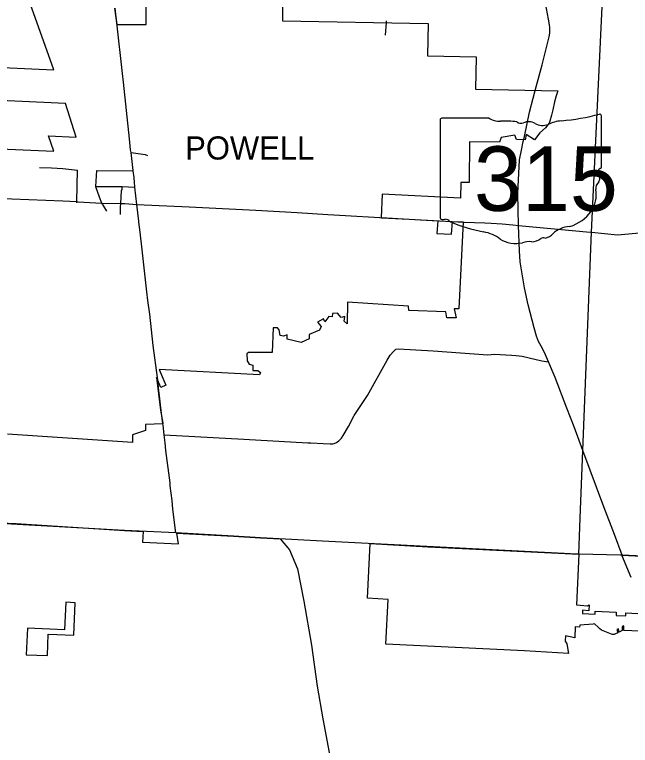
# Model space of a CAD drawing. Extents: x 1729596 to 1925846, y 659247 to 911751.
# Drawn here: x 1805067 to 1818365, y 774852 to 790627 of the extents above; entities that cross this region are included whole.
import ezdxf

# ---------------------------------------------------------------- set-up
doc = ezdxf.new("R2010")
doc.units = 0
for name, color, linetype in [('GM_X_City_Street', 7, 'Continuous'), ('GM_X_Corporation', 7, 'Continuous'), ('GM_X_Corporation_Text', 7, 'Continuous'), ('GM_X_County', 7, 'Continuous'), ('GM_X_County_Road', 7, 'Continuous'), ('GM_X_State_Route', 7, 'Continuous'), ('GM_X_State_Shield', 7, 'Continuous'), ('GM_X_Township', 7, 'Continuous'), ('GM_X_Township_Road', 7, 'Continuous')]:
    doc.layers.add(name, color=color, linetype=linetype)

msp = doc.modelspace()

# ---------------------------------------------------------------- linework, layer by layer
at = {"layer": 'GM_X_City_Street'}
for points in [[(1813075, 790181), (1813101, 790456), (1813101, 790491)], [(1807398, 789353), (1807271, 790449), (1807271, 790450)], [(1807628, 787263), (1807582, 787650), (1807569, 787707), (1807549, 787947), (1807419, 789169), (1807398, 789353)], [(1807582, 787650), (1807889, 787607), (1807940, 787583)], [(1805605, 787326), (1805861, 787317), (1806111, 787304), (1806423, 787273)], [(1806408, 786563), (1806408, 786590), (1806423, 787273)], [(1806969, 786525), (1806968, 786526), (1806959, 786540), (1806951, 786560), (1806899, 786685), (1806822, 786909), (1806822, 786916), (1806843, 787260)], [(1806843, 787260), (1807629, 787255)], [(1807709, 786531), (1807666, 786900), (1807648, 787114), (1807629, 787255), (1807628, 787263)], [(1806822, 786916), (1807392, 786917), (1807666, 786900)], [(1807356, 786480), (1807360, 786549), (1807374, 786826), (1807390, 786857), (1807392, 786917)], [(1807056, 786387), (1806969, 786525)], [(1807356, 786314), (1807356, 786472), (1807356, 786480)], [(1807750, 786168), (1807709, 786531)], [(1807947, 784457), (1807922, 784645), (1807821, 785550), (1807776, 785934), (1807752, 786147), (1807750, 786168)], [(1808158, 782748), (1808154, 782791), (1808057, 783484), (1807988, 784161), (1807947, 784457)]]:
    msp.add_lwpolyline(points, dxfattribs=at)
at = {"layer": 'GM_X_Corporation'}
for points in [[(1804164, 789513), (1805912, 789433), (1805403, 790869)], [(1810855, 790858), (1810855, 790494), (1814000, 790437), (1813987, 789737), (1815036, 789718), (1815023, 789018), (1816797, 788985), (1816759, 788876), (1816729, 788747), (1816691, 788572), (1816660, 788458), (1816629, 788327), (1816608, 788285), (1816530, 788186), (1816408, 788075), (1816292, 787922), (1816117, 788037), (1816092, 787927), (1815906, 787930), (1815870, 788024), (1815574, 787972), (1815539, 787875), (1814889, 787878), (1814886, 787002), (1814701, 787002), (1814699, 786665), (1813003, 786749), (1812982, 786246), (1813591, 786209), (1814206, 786179), (1814187, 785899), (1814503, 785888), (1814522, 786163), (1814757, 786152), (1814657, 784274), (1814557, 784275), (1814602, 784081), (1814401, 784079), (1814383, 784214), (1813584, 784242), (1813574, 784337), (1812256, 784419), (1812247, 783951), (1812181, 784013), (1812199, 784114), (1812120, 784091), (1812040, 784183), (1811933, 784175), (1811928, 784105), (1811851, 784108), (1811768, 783996), (1811741, 784063), (1811608, 783989), (1811689, 783895), (1811653, 783814), (1811428, 783724), (1811428, 783627), (1811259, 783546), (1810952, 783622), (1810951, 783717), (1810873, 783683), (1810802, 783700), (1810777, 783821), (1810744, 783865), (1810651, 783866), (1810628, 783334), (1810117, 783337), (1810085, 783303), (1810089, 783153), (1810132, 783082), (1810210, 783063), (1810211, 782942), (1810317, 782943), (1810375, 782902), (1810352, 782851), (1808190, 782970), (1808330, 782630), (1808222, 782579), (1808132, 782796), (1808214, 782091), (1808266, 781809), (1808269, 781795), (1807897, 781781), (1807895, 781653), (1807614, 781559), (1807613, 781390), (1804914, 781573)], [(1807231, 790763), (1807256, 790572), (1807273, 790417), (1807905, 790417), (1807905, 790798)], [(1804086, 787756), (1805912, 787678), (1805802, 788014), (1806394, 787983), (1806164, 788712), (1804132, 788800)], [(1803430, 774349), (1803483, 775420), (1803558, 776945), (1803585, 777445), (1803603, 778383), (1803634, 779704), (1803704, 779701), (1805102, 779639), (1807438, 779491), (1807843, 779471), (1807831, 779242), (1808605, 779201), (1808568, 779436), (1809792, 779366), (1810377, 779331), (1810804, 779309), (1811005, 779073), (1811178, 778662), (1811316, 777964), (1811480, 777017), (1811604, 776133), (1811724, 775429), (1811904, 774466)], [(1818738, 777311), (1818223, 777335), (1818227, 777430), (1818185, 777409), (1818187, 777330), (1818125, 777299), (1818105, 777371), (1818074, 777354), (1818094, 777281), (1818047, 777262), (1818016, 777249), (1817997, 777245), (1817979, 777246), (1817957, 777251), (1817918, 777268), (1817743, 777338), (1817706, 777368), (1817659, 777415), (1817598, 777471), (1817589, 777474), (1817558, 777471), (1817270, 777444), (1817267, 777407), (1817175, 777415), (1817162, 777174), (1816963, 777214), (1816955, 777103), (1816990, 777043), (1817028, 776838), (1816077, 776890), (1813084, 777036), (1813135, 778003), (1812688, 778029), (1812748, 779209), (1813989, 779140), (1817250, 778977), (1817198, 777883), (1817437, 777868), (1817477, 777883), (1817466, 777757), (1817333, 777768), (1817329, 777699), (1817602, 777686), (1817606, 777753), (1818060, 777725), (1818058, 777659), (1818265, 777648), (1818267, 777712), (1818526, 777699)], [(1818382, 778477), (1818182, 778957), (1823932, 778674)]]:
    msp.add_lwpolyline(points, dxfattribs=at)
msp.add_lwpolyline([(1805774, 776791), (1805793, 777251), (1806343, 777229), (1806372, 777932), (1806172, 777941), (1806147, 777344), (1805342, 777383), (1805319, 776810)], close=True, dxfattribs=at)
at = {"layer": 'GM_X_County'}
msp.add_lwpolyline([(1823936, 778682), (1818187, 778957), (1818151, 778958), (1817250, 778977), (1817214, 778979), (1811853, 779256), (1810377, 779331), (1809792, 779366), (1808550, 779443), (1807438, 779491), (1803704, 779701), (1803634, 779704), (1801375, 779790), (1799802, 779890), (1799218, 779920), (1797967, 779971), (1795507, 780094), (1795095, 780091), (1793746, 780223), (1793171, 780273)], dxfattribs=at)
at = {"layer": 'GM_X_County_Road'}
for points in [[(1807271, 790450), (1807231, 790763)], [(1808203, 782333), (1808174, 782570), (1808158, 782748)], [(1808272, 781763), (1808269, 781795), (1808233, 782081), (1808210, 782272), (1808203, 782333)], [(1808550, 779443), (1808487, 779955), (1808466, 780137), (1808429, 780452), (1808423, 780522), (1808336, 781219), (1808318, 781382), (1808298, 781556), (1808272, 781763)]]:
    msp.add_lwpolyline(points, dxfattribs=at)
at = {"layer": 'GM_X_State_Route'}
for points in [[(1816266, 788827), (1816308, 788989), (1816463, 789546), (1816611, 790147), (1816623, 790230), (1816624, 790350), (1816620, 790409), (1816599, 790530), (1816533, 790876), (1816487, 791123), (1816430, 791427), (1816402, 791554), (1816384, 791615), (1816350, 791700), (1816268, 791852), (1816208, 791960), (1816169, 792032), (1816020, 792294), (1815964, 792391), (1815825, 792638), (1815801, 792684), (1815789, 792708)], [(1816069, 787957), (1816079, 787999), (1816187, 788523), (1816266, 788827)], [(1816013, 787700), (1816053, 787885), (1816069, 787957)], [(1815949, 786077), (1815949, 786077), (1815938, 786769), (1815968, 787495), (1816013, 787700)], [(1804441, 786683), (1805006, 786649), (1806106, 786604), (1806408, 786590), (1806429, 786589), (1806951, 786560), (1807360, 786549), (1807446, 786547), (1807709, 786531), (1808840, 786478), (1810274, 786407), (1811167, 786357), (1811832, 786309), (1812210, 786294), (1812953, 786246)], [(1812953, 786246), (1812990, 786243), (1813591, 786209), (1814771, 786150), (1814772, 786150)], [(1814772, 786150), (1815220, 786136), (1815357, 786129), (1815594, 786109), (1815826, 786090), (1815949, 786077)], [(1815949, 786077), (1816340, 786036), (1817421, 785936), (1817504, 785931), (1817524, 785929), (1818089, 785876), (1818484, 785913), (1818908, 785967), (1819089, 785999), (1819665, 786100), (1819718, 786112), (1820036, 786168), (1820128, 786185), (1820241, 786200), (1820367, 786198), (1820698, 786179), (1821320, 786143), (1821549, 786130)], [(1818019, 779405), (1817795, 780002), (1817338, 781221), (1817148, 781730), (1816994, 782133), (1816739, 782797), (1816596, 783133), (1816530, 783286), (1816466, 783417), (1816381, 783573), (1816336, 783687), (1816285, 783865), (1816160, 784364), (1816076, 784730), (1816020, 785073), (1815987, 785293), (1815970, 785528), (1815949, 786077)], [(1818187, 778957), (1818019, 779405)]]:
    msp.add_lwpolyline(points, dxfattribs=at)
at = {"layer": 'GM_X_State_Shield'}
for p, q in [((1817739, 787338), (1817739, 788444)), ((1817739, 787338), (1817739, 788444)), ((1814259, 788355), (1814259, 786242)), ((1814259, 788355), (1814259, 786242)), ((1815312, 788391), (1814293, 788391)), ((1815312, 788391), (1814293, 788391)), ((1817739, 787339), (1817739, 787338)), ((1817739, 787339), (1817739, 787338))]:
    msp.add_line(p, q, dxfattribs=at)
for centre, major_axis, start_param, end_param in [((1816499, 791273), (3691, 0), 4.814394, 5.042369), ((1816499, 791273), (3691, 0), 4.814394, 5.042369), ((1817700, 788448), (38.7, 0), 6.141152, 7.989035), ((1817700, 788448), (38.7, 0), 6.141152, 7.989035), ((1814298, 788360), (40.3, 0), 1.712693, 3.28349), ((1814298, 788360), (40.3, 0), 1.712693, 3.28349), ((1815555, 788637), (391, 0), 4.042523, 4.731795), ((1815555, 788637), (391, 0), 4.042523, 4.731795), ((1815684, 787205), (1404, 0), 1.404758, 1.657858), ((1815684, 787205), (1404, 0), 1.404758, 1.657858), ((1816003, 788371), (113, 0), 3.836095, 5.185415), ((1816003, 788371), (113, 0), 3.836095, 5.185415), ((1816169, 788126), (235, 0), 0.950623, 2.079405), ((1816169, 788126), (235, 0), 0.950623, 2.079405), ((1816472, 788461), (282, 0), 4.081561, 5.145723), ((1816472, 788461), (282, 0), 4.081561, 5.145723), ((1816970, 787746), (743, 0), 1.699011, 2.107814), ((1816970, 787746), (743, 0), 1.699011, 2.107814), ((1817698, 787334), (41.5, 0), 5.05454, 6.418171), ((1817698, 787334), (41.5, 0), 5.05454, 6.418171), ((1817730, 787257), (60, 0), 1.883978, 3.671073), ((1817730, 787257), (60, 0), 1.883978, 3.671073), ((1817349, 787117), (360, 0), 5.934695, 6.695948), ((1817349, 787117), (360, 0), 5.934695, 6.695948), ((1817878, 786876), (262, 0), 2.387724, 3.262537), ((1817878, 786876), (262, 0), 2.387724, 3.262537), ((1816706, 786735), (923, 0), 5.101752, 6.440018), ((1816706, 786735), (923, 0), 5.101752, 6.440018), ((1814299, 786237), (40.7, 0), 3.00124, 4.508301), ((1814299, 786237), (40.7, 0), 3.00124, 4.508301), ((1814305, 786453), (310, 0), 4.665946, 4.897461), ((1814305, 786453), (310, 0), 4.665946, 4.897461), ((1814368, 786120), (112, 0), 0.519207, 1.627899), ((1814368, 786120), (112, 0), 0.519207, 1.627899), ((1815782, 788019), (2665, 0), 4.195997, 4.488961), ((1815782, 788019), (2665, 0), 4.195997, 4.488961), ((1814987, 785292), (834, 0), 0.823519, 1.323587), ((1814987, 785292), (834, 0), 0.823519, 1.323587), ((1817095, 785649), (506, 0), 1.647645, 2.488434), ((1817095, 785649), (506, 0), 1.647645, 2.488434), ((1815889, 786109), (529, 0), 4.026481, 4.996735), ((1815889, 786109), (529, 0), 4.026481, 4.996735), ((1816233, 785951), (282, 0), 4.691044, 5.507374), ((1816233, 785951), (282, 0), 4.691044, 5.507374), ((1816488, 785746), (79.4, 0), 1.147584, 2.315152), ((1816488, 785746), (79.4, 0), 1.147584, 2.315152), ((1816455, 786037), (298, 0), 4.937069, 5.64225), ((1816455, 786037), (298, 0), 4.937069, 5.64225), ((1816195, 785379), (435, 0), 1.495662, 1.94098), ((1816195, 785379), (435, 0), 1.495662, 1.94098)]:
    msp.add_ellipse(centre, major_axis=major_axis, ratio=0.8, start_param=start_param, end_param=end_param, dxfattribs=at)
at = {"layer": 'GM_X_Township'}
for points in [[(1817250, 778977), (1817281, 779754), (1817338, 781221), (1817524, 785929), (1817856, 792932), (1818194, 800042), (1818544, 806864)], [(1817250, 778977), (1817214, 778979)]]:
    msp.add_lwpolyline(points, dxfattribs=at)
at = {"layer": 'GM_X_Township_Road'}
msp.add_lwpolyline([(1808298, 781556), (1810015, 781463), (1811400, 781387), (1811432, 781386), (1811465, 781384), (1811734, 781370), (1811880, 781362), (1811937, 781365), (1811970, 781372), (1812019, 781392), (1812070, 781428), (1812129, 781487), (1812166, 781542), (1812275, 781737), (1812394, 781957), (1812402, 781975), (1812415, 781994), (1812688, 782408), (1813116, 783166), (1813176, 783276), (1813250, 783357), (1813300, 783402), (1813355, 783411), (1814105, 783369), (1815284, 783286), (1815431, 783297), (1815798, 783276), (1815898, 783270), (1816026, 783253), (1816177, 783222), (1816452, 783156), (1816596, 783133)], dxfattribs=at)

# ---------------------------------------------------------------- texts
at = {"layer": 'GM_X_Corporation_Text'}
msp.add_text('POWELL', height=500, rotation=0, dxfattribs=at).set_placement((1808751, 787499))
at = {"layer": 'GM_X_State_Shield'}
msp.add_text('315', height=1392.2, dxfattribs=at).set_placement((1814988, 786391))
msp.add_text('315', height=1392.2, dxfattribs=at).set_placement((1814988, 786391))

doc.saveas('drawing.dxf')
